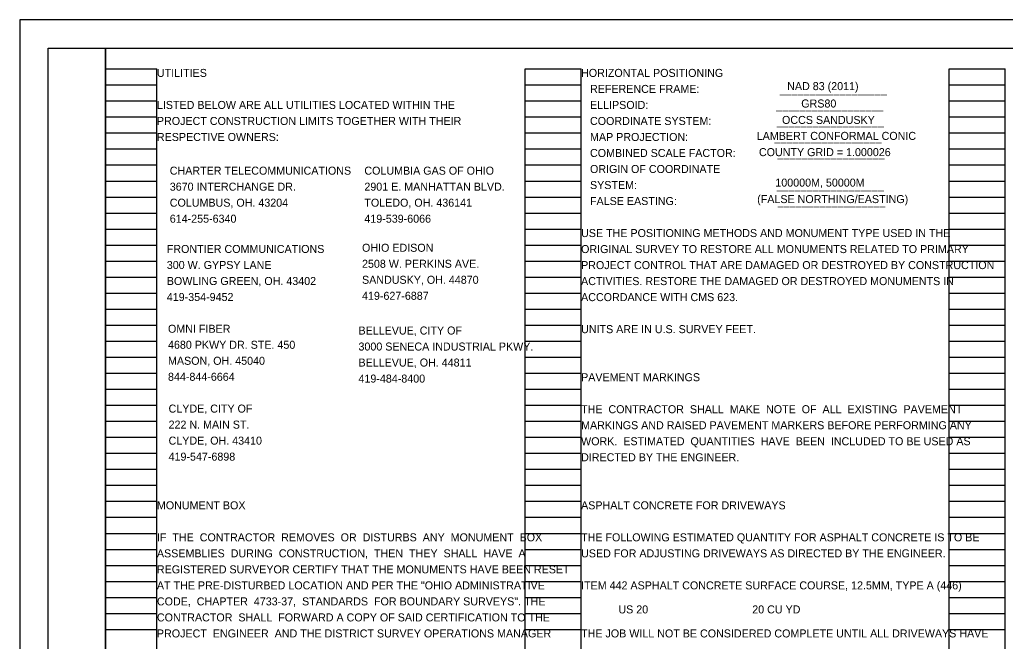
# Model space of a CAD drawing. Extents: x 0 to 34, y 0 to 22.
# Drawn here: x 0 to 17.24, y 11.13 to 22 of the extents above; entities that cross this region are included whole.
import ezdxf

# ---------------------------------------------------------------- set-up
doc = ezdxf.new("R2010")
doc.units = 0
for name, color, linetype in [('SH_Border', 7, 'Continuous'), ('SH_Cut_Line', 7, 'Continuous'), ('SH_Data', 7, 'Continuous'), ('SH_Text', 7, 'Continuous')]:
    doc.layers.add(name, color=color, linetype=linetype)

msp = doc.modelspace()

# ---------------------------------------------------------------- linework, layer by layer
at = {"layer": 'SH_Border'}
for points in [[(0.5, 21.5), (1.5, 21.5), (1.5, 0.5), (0.5, 0.5)], [(1.5, 21.5), (33.5, 21.5), (33.5, 0.5), (1.5, 0.5)]]:
    msp.add_lwpolyline(points, close=True, dxfattribs=at)
at = {"layer": 'SH_Cut_Line'}
msp.add_lwpolyline([(0, 0), (34, 0), (34, 22), (0, 22)], close=True, dxfattribs=at)
at = {"layer": 'SH_Data'}
for p, q in [((1.5, 0.98), (1.5, 21.14)), ((1.5, 21.14), (2.4, 21.14)), ((2.4, 0.98), (2.4, 21.14)), ((8.84, 0.98), (8.84, 21.14)), ((8.84, 21.14), (9.82, 21.14)), ((9.82, 0.98), (9.82, 21.14)), ((16.26, 0.98), (16.26, 21.14)), ((16.26, 21.14), (17.24, 21.14)), ((17.24, 0.98), (17.24, 21.14)), ((1.5, 20.86), (2.4, 20.86)), ((8.84, 20.86), (9.82, 20.86)), ((16.26, 20.86), (17.24, 20.86)), ((1.5, 20.58), (2.4, 20.58)), ((8.84, 20.58), (9.82, 20.58)), ((16.26, 20.58), (17.24, 20.58)), ((1.5, 20.3), (2.4, 20.3)), ((8.84, 20.3), (9.82, 20.3)), ((16.26, 20.3), (17.24, 20.3)), ((1.5, 20.02), (2.4, 20.02)), ((8.84, 20.02), (9.82, 20.02)), ((16.26, 20.02), (17.24, 20.02)), ((1.5, 19.74), (2.4, 19.74)), ((8.84, 19.74), (9.82, 19.74)), ((16.26, 19.74), (17.24, 19.74)), ((1.5, 19.46), (2.4, 19.46)), ((8.84, 19.46), (9.82, 19.46)), ((16.26, 19.46), (17.24, 19.46)), ((1.5, 19.18), (2.4, 19.18)), ((8.84, 19.18), (9.82, 19.18)), ((16.26, 19.18), (17.24, 19.18)), ((1.5, 18.9), (2.4, 18.9)), ((8.84, 18.9), (9.82, 18.9)), ((16.26, 18.9), (17.24, 18.9)), ((1.5, 18.62), (2.4, 18.62)), ((8.84, 18.62), (9.82, 18.62)), ((16.26, 18.62), (17.24, 18.62)), ((1.5, 18.34), (2.4, 18.34)), ((8.84, 18.34), (9.82, 18.34)), ((16.26, 18.34), (17.24, 18.34)), ((1.5, 18.06), (2.4, 18.06)), ((8.84, 18.06), (9.82, 18.06)), ((16.26, 18.06), (17.24, 18.06)), ((1.5, 17.78), (2.4, 17.78)), ((8.84, 17.78), (9.82, 17.78)), ((16.26, 17.78), (17.24, 17.78)), ((1.5, 17.5), (2.4, 17.5)), ((8.84, 17.5), (9.82, 17.5)), ((16.26, 17.5), (17.24, 17.5)), ((1.5, 17.22), (2.4, 17.22)), ((8.84, 17.22), (9.82, 17.22)), ((16.26, 17.22), (17.24, 17.22)), ((1.5, 16.94), (2.4, 16.94)), ((8.84, 16.94), (9.82, 16.94)), ((16.26, 16.94), (17.24, 16.94)), ((1.5, 16.66), (2.4, 16.66)), ((8.84, 16.66), (9.82, 16.66)), ((16.26, 16.66), (17.24, 16.66)), ((1.5, 16.38), (2.4, 16.38)), ((8.84, 16.38), (9.82, 16.38)), ((16.26, 16.38), (17.24, 16.38)), ((1.5, 16.1), (2.4, 16.1)), ((8.84, 16.1), (9.82, 16.1)), ((16.26, 16.1), (17.24, 16.1)), ((1.5, 15.82), (2.4, 15.82)), ((8.84, 15.82), (9.82, 15.82)), ((16.26, 15.82), (17.24, 15.82)), ((1.5, 15.54), (2.4, 15.54)), ((8.84, 15.54), (9.82, 15.54)), ((16.26, 15.54), (17.24, 15.54)), ((1.5, 15.26), (2.4, 15.26)), ((8.84, 15.26), (9.82, 15.26)), ((16.26, 15.26), (17.24, 15.26)), ((1.5, 14.98), (2.4, 14.98)), ((8.84, 14.98), (9.82, 14.98)), ((16.26, 14.98), (17.24, 14.98)), ((1.5, 14.7), (2.4, 14.7)), ((8.84, 14.7), (9.82, 14.7)), ((16.26, 14.7), (17.24, 14.7)), ((1.5, 14.42), (2.4, 14.42)), ((8.84, 14.42), (9.82, 14.42)), ((16.26, 14.42), (17.24, 14.42)), ((1.5, 14.14), (2.4, 14.14)), ((8.84, 14.14), (9.82, 14.14)), ((16.26, 14.14), (17.24, 14.14)), ((1.5, 13.86), (2.4, 13.86)), ((8.84, 13.86), (9.82, 13.86)), ((16.26, 13.86), (17.24, 13.86)), ((1.5, 13.58), (2.4, 13.58)), ((8.84, 13.58), (9.82, 13.58)), ((16.26, 13.58), (17.24, 13.58)), ((1.5, 13.3), (2.4, 13.3)), ((8.84, 13.3), (9.82, 13.3)), ((16.26, 13.3), (17.24, 13.3)), ((1.5, 13.02), (2.4, 13.02)), ((8.84, 13.02), (9.82, 13.02)), ((16.26, 13.02), (17.24, 13.02)), ((1.5, 12.74), (2.4, 12.74)), ((8.84, 12.74), (9.82, 12.74)), ((16.26, 12.74), (17.24, 12.74)), ((1.5, 12.46), (2.4, 12.46)), ((8.84, 12.46), (9.82, 12.46)), ((16.26, 12.46), (17.24, 12.46)), ((1.5, 12.18), (2.4, 12.18)), ((8.84, 12.18), (9.82, 12.18)), ((16.26, 12.18), (17.24, 12.18)), ((1.5, 11.9), (2.4, 11.9)), ((8.84, 11.9), (9.82, 11.9)), ((16.26, 11.9), (17.24, 11.9)), ((1.5, 11.62), (2.4, 11.62)), ((8.84, 11.62), (9.82, 11.62)), ((16.26, 11.62), (17.24, 11.62)), ((1.5, 11.34), (2.4, 11.34)), ((8.84, 11.34), (9.82, 11.34)), ((16.26, 11.34), (17.24, 11.34))]:
    msp.add_line(p, q, dxfattribs=at)

# ---------------------------------------------------------------- texts
at = {"layer": 'SH_Text'}
for s, p in [('UTILITIES', (2.4, 21)), ('HORIZONTAL POSITIONING', (9.82, 21)), ('   REFERENCE FRAME:                           __________________', (9.82, 20.72)), ('NAD 83 (2011)', (13.425, 20.769)), ('LISTED BELOW ARE ALL UTILITIES LOCATED WITHIN THE', (2.4, 20.44)), ('   ELLIPSOID:                                           __________________', (9.82, 20.44)), ('GRS80', (13.671, 20.465)), ('PROJECT CONSTRUCTION LIMITS TOGETHER WITH THEIR', (2.4, 20.16)), ('   COORDINATE SYSTEM:                      __________________', (9.82, 20.16)), ('OCCS SANDUSKY', (13.335, 20.178)), ('RESPECTIVE OWNERS:', (2.4, 19.88)), ('   MAP PROJECTION:                             __________________', (9.82, 19.88)), ('LAMBERT CONFORMAL CONIC', (12.892, 19.899)), ('   COMBINED SCALE FACTOR:              __________________', (9.82, 19.6)), ('COUNTY GRID = 1.000026', (12.931, 19.615)), ('CHARTER TELECOMMUNICATIONS', (2.625, 19.291)), ('COLUMBIA GAS OF OHIO', (6.029, 19.291)), ('   ORIGIN OF COORDINATE', (9.82, 19.32)), ('3670 INTERCHANGE DR.', (2.625, 19.011)), ('2901 E. MANHATTAN BLVD.', (6.029, 19.011)), ('   SYSTEM:                                               __________________', (9.82, 19.04)), ('100000M, 50000M', (13.218, 19.082)), ('COLUMBUS, OH. 43204', (2.625, 18.731)), ('TOLEDO, OH. 436141', (6.029, 18.731)), ('   FALSE EASTING:                                  __________________', (9.82, 18.76)), ('(FALSE NORTHING/EASTING)', (12.9, 18.794)), ('614-255-6340', (2.625, 18.451)), ('419-539-6066', (6.029, 18.451)), ('USE THE POSITIONING METHODS AND MONUMENT TYPE USED IN THE', (9.82, 18.2)), ('FRONTIER COMMUNICATIONS', (2.573, 17.922)), ('OHIO EDISON', (5.988, 17.943)), ('ORIGINAL SURVEY TO RESTORE ALL MONUMENTS RELATED TO PRIMARY', (9.82, 17.92)), ('300 W. GYPSY LANE', (2.573, 17.642)), ('2508 W. PERKINS AVE.', (5.988, 17.663)), ('PROJECT CONTROL THAT ARE DAMAGED OR DESTROYED BY CONSTRUCTION', (9.82, 17.64)), ('BOWLING GREEN, OH. 43402', (2.573, 17.362)), ('SANDUSKY, OH. 44870', (5.988, 17.383)), ('ACTIVITIES. RESTORE THE DAMAGED OR DESTROYED MONUMENTS IN', (9.82, 17.36)), ('419-627-6887', (5.988, 17.103)), ('419-354-9452', (2.573, 17.082)), ('ACCORDANCE WITH CMS 623.', (9.82, 17.08)), ('OMNI FIBER', (2.594, 16.527)), ('BELLEVUE, CITY OF', (5.926, 16.496)), ('UNITS ARE IN U.S. SURVEY FEET.', (9.82, 16.52)), ('4680 PKWY DR. STE. 450', (2.594, 16.247)), ('3000 SENECA INDUSTRIAL PKWY.', (5.926, 16.216)), ('MASON, OH. 45040', (2.594, 15.967)), ('BELLEVUE, OH. 44811', (5.926, 15.936)), ('844-844-6664', (2.594, 15.687)), ('419-484-8400', (5.926, 15.656)), ('PAVEMENT MARKINGS', (9.82, 15.68)), ('CLYDE, CITY OF', (2.604, 15.131)), ('THE  CONTRACTOR  SHALL  MAKE  NOTE  OF  ALL  EXISTING  PAVEMENT', (9.82, 15.12)), ('222 N. MAIN ST.', (2.604, 14.851)), ('MARKINGS AND RAISED PAVEMENT MARKERS BEFORE PERFORMING ANY', (9.82, 14.84)), ('CLYDE, OH. 43410', (2.604, 14.571)), ('WORK.  ESTIMATED  QUANTITIES  HAVE  BEEN  INCLUDED TO BE USED AS', (9.82, 14.56)), ('419-547-6898', (2.604, 14.291)), ('DIRECTED BY THE ENGINEER.', (9.82, 14.28)), ('MONUMENT BOX', (2.4, 13.44)), ('ASPHALT CONCRETE FOR DRIVEWAYS', (9.82, 13.44)), ('IF  THE  CONTRACTOR  REMOVES  OR  DISTURBS  ANY  MONUMENT  BOX', (2.4, 12.88)), ('THE FOLLOWING ESTIMATED QUANTITY FOR ASPHALT CONCRETE IS TO BE', (9.82, 12.88)), ('ASSEMBLIES  DURING  CONSTRUCTION,  THEN  THEY  SHALL  HAVE  A', (2.4, 12.6)), ('USED FOR ADJUSTING DRIVEWAYS AS DIRECTED BY THE ENGINEER.', (9.82, 12.6)), ('REGISTERED SURVEYOR CERTIFY THAT THE MONUMENTS HAVE BEEN RESET', (2.4, 12.32)), ('AT THE PRE-DISTURBED LOCATION AND PER THE "OHIO ADMINISTRATIVE', (2.4, 12.04)), ('ITEM 442 ASPHALT CONCRETE SURFACE COURSE, 12.5MM, TYPE A (446)', (9.82, 12.04)), ('CODE,  CHAPTER  4733-37,  STANDARDS  FOR BOUNDARY SURVEYS". THE', (2.4, 11.76)), ('US 20                                   20 CU YD', (10.473, 11.62)), ('CONTRACTOR  SHALL  FORWARD A COPY OF SAID CERTIFICATION TO THE', (2.4, 11.48)), ('PROJECT  ENGINEER  AND THE DISTRICT SURVEY OPERATIONS MANAGER', (2.4, 11.2)), ('THE JOB WILL NOT BE CONSIDERED COMPLETE UNTIL ALL DRIVEWAYS HAVE', (9.82, 11.2))]:
    msp.add_text(s, height=0.14, dxfattribs=at).set_placement(p)

doc.saveas('drawing.dxf')
